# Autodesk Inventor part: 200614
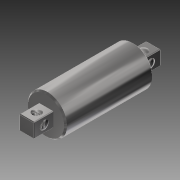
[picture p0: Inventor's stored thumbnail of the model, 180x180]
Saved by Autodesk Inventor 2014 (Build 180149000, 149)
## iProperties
Created: 2007-11
Part Number: 200614
Document SubType Name: Modeling
Designer: JJ
Density: 7.85 g/cm^3
Mass: 7.66718 g
Surface Area: 6.36635 cm^2
Volume: 0.976711 cm^3
Material: Steel
Description: MOTOR CONNECTING ROD
Appearance: Steel - Polished
Component Category: Lower Component
Author: JJ
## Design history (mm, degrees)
sketch "Sketch1"
  geometry: C1 r 4 at (0, 0); 1 further point
  constraints: 1 centre point, 1 coincident
  dimensions: "d0" = 8 diameter of C1
extrude "Extrusion1" new body sketch "Sketch1" stored distance "d1" = 18; taper "d2" = 0 deg
sketch "Sketch2"
  geometry: L1 (-5.6, 0)-(5.6, 0) reference; L2 (-1.5, -1.5)-(1.5, -1.5); L3 (1.5, -1.5)-(1.5, 1.5); L4 (1.5, 1.5)-(-1.5, 1.5); L5 (-1.5, 1.5)-(-1.5, -1.5); C1 r 4 at (0, 0) reference
  constraints: 8 end point, 2 parallel, 1 horizontal, 1 perpendicular
  dimensions: "d3" = 3 distance of L3.end L4.end (= d4); "d4" = 3 distance of L4.end L2.start; "d5" = 1.5 distance from line of C1.centre L4 (= 0.5 x d4); "d6" = 1.5 distance from line of L5 C1.centre (= 0.5 x d4)
extrude "Extrusion2" join sketch "Sketch2" distance "d7" = 4; taper "d8" = 0 deg
fillet "Fillet1" dims "d9" = 0.2
sketch "Sketch3"
  geometry: L1 (0, -4.8)-(0, 0); L2 (2.8, 0)-(2.8, -4.8); L3 (0, -2.4)-(2.8, -2.4); L4 (-4, -9)-(-4, 9) reference; L5 (-4, 9)-(4, 9) reference; L6 (4, 9)-(4, -9) reference; L7 (4, -9)-(1.5, -9) reference; L8 (1.5, -9)-(1.5, -12.8) reference; L9 (1.3, -13)-(-1.3, -13) reference; L10 (-1.5, -12.8)-(-1.5, -9) reference; L11 (-1.5, -9)-(-4, -9) reference; L12 (-1.5, -10.9)-(1.5, -10.9); L13 (1.5, -10.9)-(2.263, -10.9); L14 (-1.5, -10.9)-(-1.979, -10.9); L15 (-1.75, -10.9)-(1.75, -10.9); A1 r 1.75 centre (1.4, -2.4) between (-0.35, -2.4) and (3.15, -2.4); A2 r 0.2 centre (1.3, -12.8) between (1.3, -13) and (1.5, -12.8) reference; A3 r 0.2 centre (-1.3, -12.8) between (-1.5, -12.8) and (-1.3, -13) reference; A4 r 1.75 centre (0, -10.9) between (-1.75, -10.9) and (1.75, -10.9); 1 further point
  constraints: 14 end point, 6 midpoint, 4 point on circle, 4 point on line, 3 collinear, 2 centre point, 1 coincident
  dimensions: "d10" = 1.75 radius of A1; "d11" = 3.5 diameter of A4
revolve "Revolution1" sketch "Sketch3" stored, may be unused: angle "d12" = 90 deg
mirror "Mirror1"
chamfer "Chamfer2" distance "d16" = 0.3; stored, may be unused: second distance "d17" = 2, angle "d18" = 45 deg
workplane "Work Plane2"
split "Split2"
body "Solid1"
node "Project Cut Edges1"
other parameters: "d20" = -12.56171
